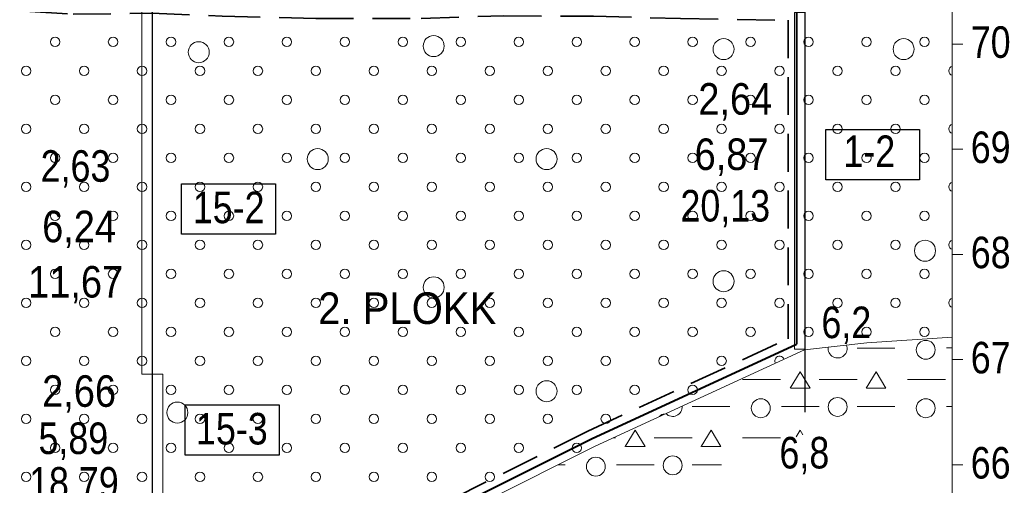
# Model space of a CAD drawing. Extents: x 640121 to 640955, y 6441885 to 6442246.
# Drawn here: x 640421.8 to 640515.9, y 6442136.1 to 6442180.3 of the extents above; entities that cross this region are included whole.
import ezdxf
from ezdxf.enums import TextEntityAlignment as Align

# ---------------------------------------------------------------- set-up
doc = ezdxf.new("R2010")
doc.units = 0
doc.header["$LTSCALE"] = 1.2
doc.linetypes.add('MEDIUM_DASHED', pattern=[4.5, 3, -1.5])
for name, color, linetype, lineweight in [('30', 7, 'Continuous', 13), ('31', 7, 'Continuous', 13), ('32', 7, 'Continuous', 13), ('33', 7, 'Continuous', 13), ('35', 7, 'Continuous', 35), ('42', 7, 'Continuous', 13), ('46', 7, 'Continuous', 13), ('47', 7, 'Continuous', 13)]:
    doc.layers.add(name, color=color, linetype=linetype, lineweight=lineweight)

msp = doc.modelspace()

# ---------------------------------------------------------------- linework, layer by layer
at = {"layer": '30'}
for p, q in [((640510.5, 6442063), (640510.5, 6442218)), ((640510.5, 6442178), (640511.5, 6442178)), ((640510.5, 6442168), (640511.5, 6442168)), ((640510.5, 6442158), (640511.5, 6442158)), ((640510.5, 6442148), (640511.5, 6442148)), ((640510.5, 6442138), (640511.5, 6442138))]:
    msp.add_line(p, q, dxfattribs=at)
at = {"layer": '31'}
msp.add_lwpolyline([(640156.71, 6442084.57), (640169.39, 6442084.94), (640174.39, 6442085), (640185.27, 6442085.01), (640198.57, 6442085.15), (640211.29, 6442085.53), (640222.23, 6442086.04), (640236.05, 6442086.58), (640247.59, 6442087.26), (640261.87, 6442089), (640272.13, 6442093.03), (640281.27, 6442096.49), (640290.79, 6442099.48), (640306.37, 6442104.48), (640328.11, 6442110.01), (640342.33, 6442112.86), (640361.6, 6442115.89), (640378.77, 6442118.83), (640434.25, 6442118.61), (640476.5, 6442139.76), (640496.42, 6442148.93), (640502.36, 6442149.59), (640510.5, 6442150.13)], dxfattribs=at)
at = {"layer": '32', "lineweight": 25}
for p, q in [((640434.37, 6442211.6), (640434.37, 6442111.6)), ((640496.47, 6442211.03), (640496.47, 6442143))]:
    msp.add_line(p, q, dxfattribs=at)
at = {"layer": '33'}
for points in [[(640433.37, 6442181.6), (640433.37, 6442146.6), (640434.36, 6442146.6), (640434.36, 6442181.6)], [(640495.47, 6442181), (640495.47, 6442149), (640496.42, 6442149), (640496.47, 6442149), (640496.47, 6442181), (640496.4, 6442181)], [(640435.37, 6442131.6), (640435.37, 6442146.6), (640434.36, 6442146.6), (640434.37, 6442131.6)]]:
    msp.add_lwpolyline(points, close=True, dxfattribs=at)
at = {"layer": '33', "lineweight": 25}
for points in [[(640498.45, 6442169.88), (640507.37, 6442169.88), (640507.37, 6442165.1), (640498.45, 6442165.1)], [(640437.16, 6442164.71), (640446.08, 6442164.71), (640446.08, 6442159.93), (640437.16, 6442159.93)], [(640437.51, 6442143.69), (640446.44, 6442143.69), (640446.44, 6442138.91), (640437.51, 6442138.91)]]:
    msp.add_lwpolyline(points, close=True, dxfattribs=at)
at = {"layer": '35', "lineweight": 40}
msp.add_line((640495.67, 6442206.13), (640495.67, 6442149.47), dxfattribs=at)
at = {"layer": '35', "linetype": 'MEDIUM_DASHED'}
msp.add_line((640494.87, 6442180.27), (640494.87, 6442149.98), dxfattribs=at)
for points in [[(640377.97, 6442182.13), (640382.89, 6442182.48), (640390.58, 6442182.59), (640398.33, 6442182.54), (640407.37, 6442182.04), (640417.33, 6442181.44), (640426.83, 6442180.84), (640434.31, 6442180.94), (640441.03, 6442180.66), (640449.92, 6442180.42), (640459.94, 6442180.44), (640467.82, 6442180.69), (640476.36, 6442180.64), (640484.62, 6442180.44), (640494.87, 6442180.27)], [(640433.96, 6442120.25), (640475.81, 6442141.2), (640494.87, 6442149.98)]]:
    msp.add_lwpolyline(points, dxfattribs=at)
at = {"layer": '35', "lineweight": 40}
msp.add_lwpolyline([(640434.15, 6442119.45), (640476.16, 6442140.48), (640495.67, 6442149.47)], dxfattribs=at)
at = {"layer": '42'}
for centre in [(640425.12, 6442178.213), (640430.636, 6442178.213), (640436.151, 6442178.213), (640441.666, 6442178.213), (640447.182, 6442178.213), (640452.697, 6442178.213), (640458.213, 6442178.213), (640463.728, 6442178.213), (640469.244, 6442178.213), (640474.759, 6442178.213), (640480.274, 6442178.213), (640485.79, 6442178.213), (640491.305, 6442178.213), (640496.821, 6442178.213), (640502.336, 6442178.213), (640507.852, 6442178.213), (640422.362, 6442175.455), (640427.878, 6442175.455), (640433.393, 6442175.455), (640438.909, 6442175.455), (640444.424, 6442175.455), (640449.94, 6442175.455), (640455.455, 6442175.455), (640460.97, 6442175.455), (640466.486, 6442175.455), (640472.001, 6442175.455), (640477.517, 6442175.455), (640483.032, 6442175.455), (640488.548, 6442175.455), (640494.063, 6442175.455), (640499.578, 6442175.455), (640505.094, 6442175.455), (640425.12, 6442172.697), (640430.636, 6442172.697), (640436.151, 6442172.697), (640441.666, 6442172.697), (640447.182, 6442172.697), (640452.697, 6442172.697), (640458.213, 6442172.697), (640463.728, 6442172.697), (640469.244, 6442172.697), (640474.759, 6442172.697), (640480.274, 6442172.697), (640485.79, 6442172.697), (640491.305, 6442172.697), (640496.821, 6442172.697), (640502.336, 6442172.697), (640507.852, 6442172.697), (640422.362, 6442169.94), (640427.878, 6442169.94), (640433.393, 6442169.94), (640438.909, 6442169.94), (640444.424, 6442169.94), (640449.94, 6442169.94), (640455.455, 6442169.94), (640460.97, 6442169.94), (640466.486, 6442169.94), (640472.001, 6442169.94), (640477.517, 6442169.94), (640483.032, 6442169.94), (640488.548, 6442169.94), (640494.063, 6442169.94), (640499.578, 6442169.94), (640505.094, 6442169.94), (640425.12, 6442167.182), (640430.636, 6442167.182), (640436.151, 6442167.182), (640441.666, 6442167.182), (640447.182, 6442167.182), (640452.697, 6442167.182), (640458.213, 6442167.182), (640463.728, 6442167.182), (640469.244, 6442167.182), (640474.759, 6442167.182), (640480.274, 6442167.182), (640485.79, 6442167.182), (640491.305, 6442167.182), (640496.821, 6442167.182), (640502.336, 6442167.182), (640507.852, 6442167.182), (640422.362, 6442164.424), (640427.878, 6442164.424), (640433.393, 6442164.424), (640438.909, 6442164.424), (640444.424, 6442164.424), (640449.94, 6442164.424), (640455.455, 6442164.424), (640460.97, 6442164.424), (640466.486, 6442164.424), (640472.001, 6442164.424), (640477.517, 6442164.424), (640483.032, 6442164.424), (640488.548, 6442164.424), (640494.063, 6442164.424), (640499.578, 6442164.424), (640505.094, 6442164.424), (640425.12, 6442161.667), (640430.636, 6442161.667), (640436.151, 6442161.667), (640441.666, 6442161.667), (640447.182, 6442161.667), (640452.697, 6442161.667), (640458.213, 6442161.667), (640463.728, 6442161.667), (640469.244, 6442161.667), (640474.759, 6442161.667), (640480.274, 6442161.667), (640485.79, 6442161.667), (640491.305, 6442161.667), (640496.821, 6442161.667), (640502.336, 6442161.667), (640507.852, 6442161.667), (640422.362, 6442158.909), (640427.878, 6442158.909), (640433.393, 6442158.909), (640438.909, 6442158.909), (640444.424, 6442158.909), (640449.94, 6442158.909), (640455.455, 6442158.909), (640460.97, 6442158.909), (640466.486, 6442158.909), (640472.001, 6442158.909), (640477.517, 6442158.909), (640483.032, 6442158.909), (640488.548, 6442158.909), (640494.063, 6442158.909), (640499.578, 6442158.909), (640505.094, 6442158.909), (640425.12, 6442156.151), (640430.636, 6442156.151), (640436.151, 6442156.151), (640441.666, 6442156.151), (640447.182, 6442156.151), (640452.697, 6442156.151), (640458.213, 6442156.151), (640463.728, 6442156.151), (640469.244, 6442156.151), (640474.759, 6442156.151), (640480.274, 6442156.151), (640485.79, 6442156.151), (640491.305, 6442156.151), (640496.821, 6442156.151), (640502.336, 6442156.151), (640507.852, 6442156.151), (640422.362, 6442153.393), (640427.878, 6442153.393), (640433.393, 6442153.393), (640438.909, 6442153.393), (640444.424, 6442153.393), (640449.94, 6442153.393), (640455.455, 6442153.393), (640460.97, 6442153.393), (640466.486, 6442153.393), (640472.001, 6442153.393), (640477.517, 6442153.393), (640483.032, 6442153.393), (640488.548, 6442153.393), (640494.063, 6442153.393), (640499.578, 6442153.393), (640505.094, 6442153.393), (640425.12, 6442150.636), (640430.636, 6442150.636), (640436.151, 6442150.636), (640441.666, 6442150.636), (640447.182, 6442150.636), (640452.697, 6442150.636), (640458.213, 6442150.636), (640463.728, 6442150.636), (640469.244, 6442150.636), (640474.759, 6442150.636), (640480.274, 6442150.636), (640485.79, 6442150.636), (640491.305, 6442150.636), (640496.821, 6442150.636), (640502.336, 6442150.636), (640507.852, 6442150.636), (640422.362, 6442147.878), (640427.878, 6442147.878), (640433.393, 6442147.878), (640438.909, 6442147.878), (640444.424, 6442147.878), (640449.94, 6442147.878), (640455.455, 6442147.878), (640460.97, 6442147.878), (640466.486, 6442147.878), (640472.001, 6442147.878), (640477.517, 6442147.878), (640483.032, 6442147.878), (640488.548, 6442147.878), (640425.12, 6442145.12), (640430.636, 6442145.12), (640436.151, 6442145.12), (640441.666, 6442145.12), (640447.182, 6442145.12), (640452.697, 6442145.12), (640458.213, 6442145.12), (640463.728, 6442145.12), (640469.244, 6442145.12), (640474.759, 6442145.12), (640480.274, 6442145.12), (640485.79, 6442145.12), (640422.362, 6442142.363), (640427.878, 6442142.363), (640433.393, 6442142.363), (640438.909, 6442142.363), (640444.424, 6442142.363), (640449.94, 6442142.363), (640455.455, 6442142.363), (640460.97, 6442142.363), (640466.486, 6442142.363), (640472.001, 6442142.363), (640477.517, 6442142.363), (640425.12, 6442139.605), (640430.636, 6442139.605), (640436.151, 6442139.605), (640441.666, 6442139.605), (640447.182, 6442139.605), (640452.697, 6442139.605), (640458.213, 6442139.605), (640463.728, 6442139.605), (640469.244, 6442139.605), (640474.759, 6442139.605), (640422.362, 6442136.847), (640427.878, 6442136.847), (640433.393, 6442136.847), (640438.909, 6442136.847), (640444.424, 6442136.847), (640449.94, 6442136.847), (640455.455, 6442136.847), (640460.97, 6442136.847), (640466.486, 6442136.847)]:
    msp.add_circle(centre, 0.45, dxfattribs=at)
for centre, start, end in [((640510.609, 6442175.455), 103.42148, 256.57852), ((640510.609, 6442169.94), 103.42148, 256.57852), ((640510.609, 6442164.424), 103.42148, 256.57852), ((640510.609, 6442158.909), 103.42148, 256.57852), ((640510.609, 6442153.393), 103.42148, 256.57852), ((640494.063, 6442147.878), 21.25506, 208.22411), ((640483.032, 6442142.363), 79.05621, 150.42296)]:
    msp.add_arc(centre, 0.45, start, end, dxfattribs=at)
at = {"layer": '46'}
for p, q in [((640505.04, 6442149.1), (640501.44, 6442149.1)), ((640510.5, 6442149.11), (640509.93, 6442149.11)), ((640494.14, 6442146.11), (640490.54, 6442146.11)), ((640501.44, 6442146.11), (640497.84, 6442146.11)), ((640509.84, 6442146.11), (640506.24, 6442146.11)), ((640489.34, 6442143.55), (640485.74, 6442143.55)), ((640497.84, 6442143.55), (640494.24, 6442143.55)), ((640505.04, 6442143.55), (640501.44, 6442143.55)), ((640510.5, 6442143.55), (640509.93, 6442143.55)), ((640478.45, 6442140.55), (640478.24, 6442140.55)), ((640485.74, 6442140.55), (640482.14, 6442140.55)), ((640494.14, 6442140.55), (640490.54, 6442140.55)), ((640473.65, 6442137.99), (640472.98, 6442137.99)), ((640482.14, 6442138), (640478.54, 6442138)), ((640488.52, 6442137.99), (640485.74, 6442137.99))]:
    msp.add_line(p, q, dxfattribs=at)
for points in [[(640495.08, 6442145.28), (640495.08, 6442145.3), (640496.03, 6442146.83), (640496.96, 6442145.29), (640495.16, 6442145.3)], [(640502.3, 6442145.28), (640502.3, 6442145.3), (640503.25, 6442146.83), (640504.18, 6442145.29), (640502.38, 6442145.3)], [(640479.38, 6442139.72), (640479.38, 6442139.75), (640480.33, 6442141.28), (640481.26, 6442139.74), (640479.46, 6442139.75)], [(640486.6, 6442139.72), (640486.61, 6442139.75), (640487.55, 6442141.28), (640488.48, 6442139.74), (640486.68, 6442139.75)], [(640495.64, 6442140.65), (640496.03, 6442141.28), (640496.29, 6442140.84)]]:
    msp.add_lwpolyline(points, dxfattribs=at)
for centre in [(640507.968, 6442148.931), (640492.273, 6442143.377), (640499.586, 6442143.499), (640507.968, 6442143.377), (640476.578, 6442137.823), (640483.891, 6442137.945)]:
    msp.add_circle(centre, 0.9, dxfattribs=at)
for centre, start, end in [((640499.586, 6442149.054), 171.65311, 20.98397), ((640483.891, 6442143.499), 224.71286, 4.76631)]:
    msp.add_arc(centre, 0.9, start, end, dxfattribs=at)
at = {"layer": '47'}
for centre in [(640461.148, 6442177.81), (640488.735, 6442177.52), (640505.868, 6442177.52), (640438.789, 6442177.23), (640450.114, 6442167.066), (640471.893, 6442167.066), (640507.901, 6442158.355), (640461.148, 6442154.87), (640488.735, 6442155.451), (640471.893, 6442144.997), (640436.756, 6442142.964)]:
    msp.add_circle(centre, 1, dxfattribs=at)

# ---------------------------------------------------------------- texts
at = {"layer": '30', "width": 0.85}
for s, p in [('70', (640514.15, 6442176.69)), ('69', (640514.15, 6442166.69)), ('68', (640514.155, 6442156.69)), ('67', (640514.15, 6442146.69)), ('66', (640514.15, 6442136.69))]:
    msp.add_text(s, height=3, dxfattribs=at).set_placement(p, align=Align.CENTER)
at = {"layer": '32'}
for s, width, p in [('2,64', 0.9, (640489.845, 6442171.29)), ('2,63', 0.85, (640427.065, 6442164.91)), ('20,13', 0.85, (640488.895, 6442161.13)), ('11,67', 0.9, (640427.075, 6442153.9)), ('6,2', 0.85, (640500.415, 6442150.04)), ('2,66', 0.9, (640427.405, 6442143.51)), ('6,8', 0.85, (640496.42, 6442137.65)), ('18,79', 0.85, (640426.91, 6442134.78))]:
    msp.add_text(s, height=3, dxfattribs=dict(at, width=width)).set_placement(p, align=Align.CENTER)
at = {"layer": '33'}
for s, width, p in [('6,87', 0.9, (640489.49, 6442166.03)), ('1-2', 0.85, (640502.6, 6442166.31)), ('15-2', 0.85, (640441.635, 6442160.97)), ('6,24', 0.9, (640427.405, 6442159.16)), ('15-3', 0.85, (640441.94, 6442139.93)), ('5,89', 0.85, (640426.86, 6442139.02))]:
    msp.add_text(s, height=3, dxfattribs=dict(at, width=width)).set_placement(p, align=Align.CENTER)
at = {"layer": '35', "width": 0.95}
msp.add_text('2. PLOKK', height=3, dxfattribs=at).set_placement((640458.63, 6442151.39), align=Align.CENTER)

doc.saveas('drawing.dxf')
